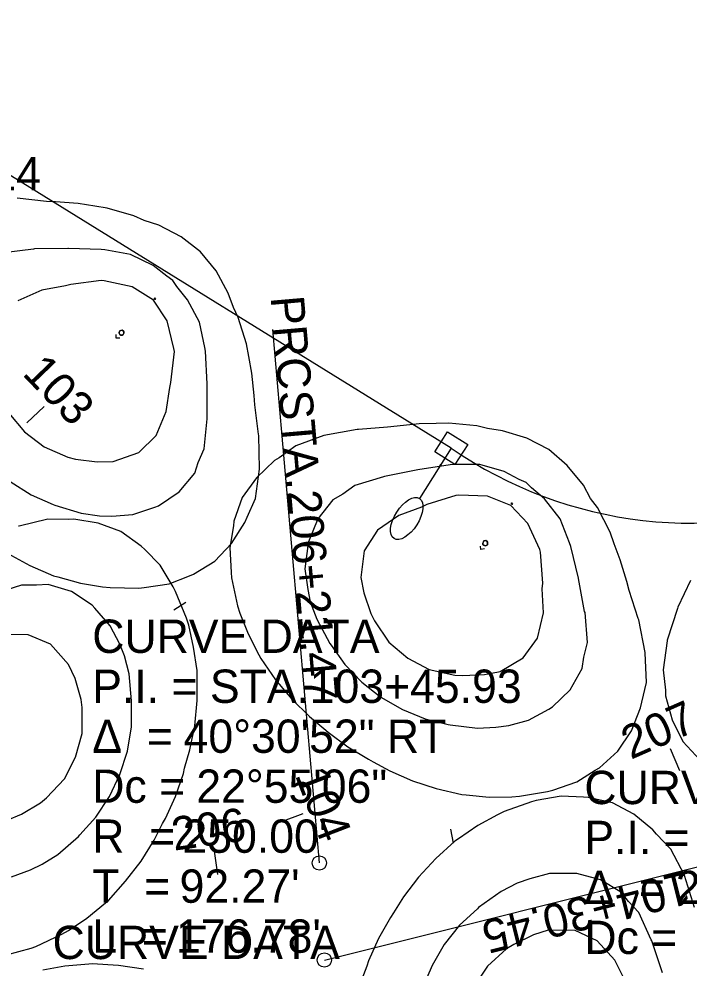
# Model space of a CAD drawing. Extents: x 1598538 to 1602183, y 285823 to 288192.
# Drawn here: x 1600950.3 to 1601091, y 286669.9 to 286869.3 of the extents above; entities that cross this region are included whole.
import ezdxf

# ---------------------------------------------------------------- set-up
doc = ezdxf.new("R2010")
doc.units = 0
for name, color, linetype in [('CM_Corridor_Conceptual', 7, 'Continuous'), ('Default', 7, 'Continuous'), ('MD_P_AGB_B', 7, 'Continuous'), ('PV_P_Curb', 7, 'Continuous'), ('RW_P_Esmt_LA', 7, 'Continuous'), ('RW_P_Esmt_TMP', 7, 'Continuous')]:
    doc.layers.add(name, color=color, linetype=linetype)

msp = doc.modelspace()

# ---------------------------------------------------------------- linework, layer by layer
at = {"layer": 'Default'}
for points in [[(1600947.92, 286756.99), (1600952.55, 286754.46), (1600957.55, 286752.3), (1600958.42, 286752.05), (1600963.17, 286750.74), (1600967.8, 286749.96), (1600969.42, 286749.8), (1600975.42, 286749.68), (1600976.55, 286749.8), (1600981.8, 286750.58), (1600986.05, 286752.27), (1600986.92, 286752.61), (1600991.42, 286755.36), (1600994.92, 286759.08), (1600997.67, 286763.52), (1600998.17, 286764.61), (1600999.92, 286768.55), (1601000.8, 286774.68), (1601000.8, 286774.74), (1601000.67, 286781.77), (1601000.55, 286782.08), (1600999.8, 286788.21), (1600999.67, 286790.18), (1600999.17, 286794.86), (1600998.55, 286798.4), (1600998.05, 286801.02), (1600996.3, 286806.55), (1600995.3, 286808.68), (1600994.17, 286811.71), (1600991.67, 286816.4), (1600988.42, 286820.36), (1600984.3, 286823.52), (1600979.67, 286825.96), (1600976.55, 286826.96), (1600974.42, 286827.93), (1600968.8, 286829.52), (1600966.17, 286829.93), (1600962.67, 286830.49), (1600957.92, 286830.86), (1600956.05, 286830.96), (1600949.92, 286831.65)], [(1600948.42, 286772.11), (1600952.8, 286769.3), (1600957.42, 286767.3), (1600957.8, 286767.11), (1600963.3, 286765.43), (1600967.17, 286764.9), (1600969.8, 286764.83), (1600974.17, 286765.18), (1600978.8, 286766.71), (1600979.55, 286766.99), (1600983.92, 286769.9), (1600987.17, 286773.83), (1600987.92, 286776.11), (1600989.17, 286778.99), (1600989.8, 286785.27), (1600989.8, 286785.49), (1600989.8, 286792.58), (1600989.8, 286792.65), (1600989.42, 286799.46), (1600989.3, 286800.27), (1600988.17, 286805.55), (1600985.67, 286810.3), (1600983.42, 286813.08), (1600982.55, 286814.33), (1600981.3, 286815.27), (1600978.42, 286817.46), (1600973.67, 286819.83), (1600968.3, 286820.77), (1600967.55, 286820.83), (1600960.67, 286821.08), (1600960.55, 286821.08), (1600953.55, 286820.96), (1600953.3, 286820.93), (1600947.05, 286820.15)], [(1600948.17, 286786.49), (1600951.42, 286782.52), (1600955.55, 286779.36), (1600960.55, 286777.24), (1600962.17, 286776.83), (1600966.67, 286776.24), (1600970.05, 286776.33), (1600975.42, 286778.21), (1600979.05, 286781.77), (1600981.17, 286786.8), (1600981.92, 286791.83), (1600982.17, 286792.93), (1600982.92, 286799.43), (1600982.8, 286800.02), (1600981.42, 286805.86), (1600978.55, 286810.21), (1600974.05, 286812.99), (1600968.17, 286814.3), (1600967.55, 286814.33), (1600961.17, 286813.52), (1600960.05, 286813.21), (1600955.05, 286812.33), (1600950.05, 286810.08)], [(1600971.42, 286802.24), (1600970.67, 286802.24), (1600970.67, 286802.99)], [(1601053.8, 286767.24), (1601053.92, 286767.46), (1601053.92, 286767.46), (1601053.8, 286767.24), (1601053.8, 286767.24)], [(1600947.67, 286672.65), (1600952.8, 286674.05), (1600953.8, 286674.4), (1600959.3, 286676.96), (1600960.67, 286677.77), (1600964.55, 286680.36), (1600968.42, 286683.55), (1600969.05, 286684.08), (1600972.67, 286688.11), (1600975.92, 286692.33), (1600978.67, 286696.74), (1600980.42, 286700.27), (1600981.05, 286701.3), (1600983.17, 286705.93), (1600984.8, 286710.77), (1600985.05, 286711.9), (1600986.17, 286715.71), (1600987.17, 286720.8), (1600987.67, 286726.08), (1600987.67, 286731.55), (1600987.67, 286732.36), (1600986.92, 286737.3), (1600985.92, 286741.9), (1600985.42, 286743.4), (1600983.17, 286748.99), (1600982.67, 286749.96), (1600979.92, 286754.49), (1600976.67, 286757.8), (1600975.92, 286758.52), (1600971.67, 286761.61), (1600966.92, 286763.36), (1600961.8, 286764.21), (1600960.67, 286764.15), (1600956.3, 286764.21), (1600950.3, 286762.71), (1600950.17, 286762.71)], [(1601047.8, 286759.43), (1601047.67, 286759.18), (1601047.67, 286759.18), (1601047.8, 286759.43), (1601047.8, 286759.43)], [(1601048.67, 286759.36), (1601048.55, 286759.58), (1601048.55, 286759.58), (1601048.67, 286759.36), (1601048.67, 286759.36)], [(1601048.05, 286757.96), (1601047.3, 286757.83), (1601047.17, 286758.55)], [(1601047.67, 286758.9), (1601047.92, 286758.71), (1601047.92, 286758.71), (1601047.67, 286758.9), (1601047.67, 286758.9)], [(1601048.42, 286758.68), (1601048.67, 286758.83), (1601048.67, 286758.83), (1601048.42, 286758.68), (1601048.42, 286758.68)], [(1601091.3, 286751.3), (1601088.67, 286745.71), (1601088.55, 286745.43), (1601086.42, 286738.74), (1601086.42, 286738.65), (1601085.55, 286732.52), (1601086.05, 286728.24), (1601086.05, 286727.08), (1601087.42, 286722.05), (1601089.67, 286717.46), (1601093.3, 286713.55)], [(1600948.67, 286689.05), (1600952.67, 286690.52), (1600955.17, 286691.68), (1600958.42, 286693.74), (1600962.8, 286697.52), (1600963.05, 286697.86), (1600966.42, 286701.58), (1600969.3, 286705.93), (1600971.42, 286710.55), (1600973.05, 286715.43), (1600973.92, 286720.55), (1600973.92, 286725.55), (1600973.92, 286725.99), (1600973.42, 286731.71), (1600972.42, 286735.46), (1600971.42, 286737.96), (1600969.42, 286741.8), (1600966.17, 286745.49), (1600965.67, 286746.11), (1600961.3, 286748.96), (1600956.42, 286750.46), (1600953.92, 286750.3), (1600950.8, 286750.3), (1600944.8, 286748.46)], [(1600947.8, 286700.93), (1600950.8, 286702.21), (1600954.8, 286704.58), (1600956.05, 286705.61), (1600959.8, 286709.65), (1600962.17, 286714.18), (1600963.55, 286719.15), (1600963.55, 286724.61), (1600963.3, 286726.27), (1600962.05, 286730.68), (1600960.67, 286733.68), (1600956.92, 286737.9), (1600952.17, 286739.9), (1600946.67, 286739.93)], [(1601092.17, 286682.58), (1601090.05, 286689.33), (1601090.05, 286689.4), (1601087.17, 286694.86), (1601084.17, 286698.02), (1601083.42, 286698.93), (1601079.42, 286702.24), (1601074.92, 286704.61), (1601069.8, 286705.74), (1601068.8, 286705.8), (1601064.17, 286705.99), (1601058.92, 286705.05), (1601057.92, 286704.8), (1601052.17, 286702.74), (1601050.8, 286702.05), (1601046.67, 286699.83), (1601042.55, 286697.02), (1601041.8, 286696.55), (1601037.8, 286692.86), (1601034.17, 286688.96), (1601031.05, 286684.83), (1601028.92, 286681.46), (1601028.3, 286680.52), (1601025.8, 286676.08), (1601023.67, 286671.4), (1601023.3, 286670.3), (1601021.92, 286666.61)], [(1601085.42, 286668.86), (1601083.17, 286675.58), (1601083.05, 286675.77), (1601080.42, 286681.52), (1601078.3, 286683.86), (1601076.8, 286685.74), (1601072.42, 286688.4), (1601067.42, 286689.77), (1601066.55, 286689.77), (1601061.67, 286689.74), (1601057.55, 286688.65), (1601054.92, 286687.71), (1601051.55, 286685.96), (1601046.8, 286682.58), (1601046.55, 286682.3), (1601042.8, 286678.9), (1601039.55, 286674.83), (1601037.05, 286670.4), (1601035.05, 286665.71)], [(1601077.67, 286667.05), (1601075.42, 286671.55), (1601071.67, 286675.61), (1601067.05, 286677.77), (1601061.42, 286677.83), (1601058.3, 286676.83), (1601054.17, 286674.8), (1601052.67, 286673.9), (1601048.67, 286670.24), (1601045.8, 286665.96)], [(1600976.42, 286669.65), (1600971.17, 286670.43), (1600965.67, 286670.74), (1600964.92, 286670.68), (1600959.92, 286670.27), (1600955.3, 286669.4)]]:
    msp.add_lwpolyline(points, dxfattribs=at)
for points in [[(1600978.92, 286810.52), (1600978.8, 286810.71), (1600978.67, 286810.52), (1600978.8, 286810.33)], [(1600978.92, 286810.52), (1600978.8, 286810.71), (1600978.67, 286810.52), (1600978.8, 286810.33)], [(1600978.8, 286810.71), (1600978.67, 286810.52), (1600978.67, 286810.52), (1600978.8, 286810.71)], [(1600978.67, 286810.52), (1600978.8, 286810.33), (1600978.8, 286810.33), (1600978.67, 286810.52)], [(1600978.92, 286810.52), (1600978.8, 286810.71), (1600978.8, 286810.71), (1600978.92, 286810.52)], [(1600978.8, 286810.33), (1600978.92, 286810.52), (1600978.92, 286810.52), (1600978.8, 286810.33)], [(1600972.3, 286803.24), (1600972.3, 286803.52), (1600972.17, 286803.74), (1600971.92, 286803.9), (1600971.67, 286803.86), (1600971.42, 286803.74), (1600971.3, 286803.49), (1600971.3, 286803.24), (1600971.42, 286802.99), (1600971.67, 286802.86), (1600971.92, 286802.86), (1600972.17, 286802.99)], [(1600972.3, 286803.24), (1600972.3, 286803.52), (1600972.17, 286803.74), (1600971.92, 286803.9), (1600971.67, 286803.86), (1600971.42, 286803.74), (1600971.3, 286803.49), (1600971.3, 286803.24), (1600971.42, 286802.99), (1600971.67, 286802.86), (1600971.92, 286802.86), (1600972.17, 286802.99)], [(1600971.42, 286803.74), (1600971.3, 286803.49), (1600971.3, 286803.49), (1600971.42, 286803.74)], [(1600971.3, 286803.49), (1600971.3, 286803.24), (1600971.3, 286803.24), (1600971.3, 286803.49)], [(1600971.3, 286803.24), (1600971.42, 286802.99), (1600971.42, 286802.99), (1600971.3, 286803.24)], [(1600971.67, 286803.86), (1600971.42, 286803.74), (1600971.42, 286803.74), (1600971.67, 286803.86)], [(1600971.92, 286803.9), (1600971.67, 286803.86), (1600971.67, 286803.86), (1600971.92, 286803.9)], [(1600972.17, 286803.74), (1600971.92, 286803.9), (1600971.92, 286803.9), (1600972.17, 286803.74)], [(1600972.3, 286803.52), (1600972.17, 286803.74), (1600972.17, 286803.74), (1600972.3, 286803.52)], [(1600972.17, 286802.99), (1600972.3, 286803.24), (1600972.3, 286803.24), (1600972.17, 286802.99)], [(1600972.3, 286803.24), (1600972.3, 286803.52), (1600972.3, 286803.52), (1600972.3, 286803.24)], [(1600971.42, 286802.99), (1600971.67, 286802.86), (1600971.67, 286802.86), (1600971.42, 286802.99)], [(1600971.67, 286802.86), (1600971.92, 286802.86), (1600971.92, 286802.86), (1600971.67, 286802.86)], [(1600971.92, 286802.86), (1600972.17, 286802.99), (1600972.17, 286802.99), (1600971.92, 286802.86)], [(1600995.42, 286763.77), (1600995.3, 286762.8), (1600994.55, 286758.24), (1600994.8, 286752.96), (1600994.92, 286751.83), (1600996.17, 286745.96), (1600996.67, 286744.46), (1600998.42, 286740.08), (1601000.67, 286735.65), (1601001.05, 286734.9), (1601004.17, 286730.43), (1601007.55, 286726.36), (1601011.3, 286722.74), (1601014.3, 286720.21), (1601015.17, 286719.46), (1601019.3, 286716.36), (1601023.67, 286713.74), (1601024.67, 286713.21), (1601028.17, 286711.33), (1601032.92, 286709.24), (1601037.92, 286707.58), (1601043.3, 286706.33), (1601044.17, 286706.24), (1601049.05, 286705.8), (1601053.8, 286705.86), (1601055.42, 286705.99), (1601061.3, 286706.96), (1601062.42, 286707.27), (1601067.42, 286708.99), (1601071.3, 286711.43), (1601072.17, 286711.93), (1601076.05, 286715.43), (1601078.92, 286719.71), (1601080.8, 286724.55), (1601081.05, 286725.71), (1601082.05, 286729.9), (1601081.8, 286736.08), (1601081.8, 286736.15), (1601080.42, 286743.05), (1601080.3, 286743.33), (1601078.42, 286749.21), (1601077.92, 286751.11), (1601076.55, 286755.65), (1601075.3, 286759.02), (1601074.42, 286761.49), (1601071.8, 286766.65), (1601070.3, 286768.55), (1601068.8, 286771.33), (1601065.42, 286775.49), (1601061.55, 286778.83), (1601056.92, 286781.21), (1601051.8, 286782.77), (1601048.67, 286783.21), (1601046.42, 286783.77), (1601040.55, 286784.33), (1601037.92, 286784.3), (1601034.3, 286784.21), (1601029.67, 286783.74), (1601027.67, 286783.49), (1601021.55, 286783.05), (1601021.3, 286783.02), (1601014.3, 286781.8), (1601014.3, 286781.77), (1601008.42, 286779.61), (1601004.92, 286777.11), (1601003.92, 286776.49), (1601000.17, 286772.9), (1600997.17, 286768.74)], [(1601011.05, 286759.43), (1601010.92, 286758.58), (1601010.3, 286753.74), (1601010.92, 286749.43), (1601011.42, 286746.8), (1601012.8, 286743.15), (1601015.55, 286738.08), (1601015.8, 286737.74), (1601018.67, 286733.68), (1601022.3, 286729.93), (1601026.3, 286726.8), (1601030.8, 286724.21), (1601035.55, 286722.24), (1601040.42, 286721.05), (1601040.8, 286720.96), (1601046.55, 286720.3), (1601050.42, 286720.46), (1601053.17, 286720.86), (1601057.3, 286721.96), (1601061.55, 286724.3), (1601062.3, 286724.74), (1601066.05, 286728.36), (1601068.55, 286732.83), (1601068.92, 286735.21), (1601069.67, 286738.27), (1601069.17, 286744.55), (1601069.05, 286744.77), (1601067.8, 286751.71), (1601067.8, 286751.8), (1601066.17, 286758.43), (1601065.92, 286759.21), (1601063.92, 286764.24), (1601060.67, 286768.46), (1601057.92, 286770.77), (1601056.8, 286771.86), (1601055.3, 286772.52), (1601052.17, 286774.18), (1601047.05, 286775.65), (1601041.67, 286775.65), (1601040.8, 286775.58), (1601034.05, 286774.58), (1601034.05, 286774.58), (1601027.05, 286773.18), (1601026.8, 286773.11), (1601020.8, 286771.24), (1601018.3, 286769.46), (1601016.17, 286768.24), (1601013.05, 286764.24)], [(1601022.05, 286751.93), (1601022.67, 286748.68), (1601024.17, 286744.36), (1601024.92, 286742.83), (1601027.92, 286738.33), (1601031.92, 286734.99), (1601036.42, 286732.61), (1601041.8, 286731.43), (1601043.42, 286731.33), (1601048.05, 286731.55), (1601051.3, 286732.21), (1601056.17, 286735.02), (1601059.17, 286739.18), (1601060.42, 286744.52), (1601060.17, 286749.58), (1601060.3, 286750.71), (1601059.8, 286757.24), (1601059.67, 286757.83), (1601057.17, 286763.3), (1601053.55, 286767.05), (1601048.67, 286769.02), (1601042.67, 286769.24), (1601042.05, 286769.18), (1601035.92, 286767.24), (1601034.8, 286766.71), (1601030.05, 286764.99), (1601025.55, 286761.86), (1601022.8, 286757.55)], [(1601053.92, 286767.46), (1601053.8, 286767.61), (1601053.67, 286767.4), (1601053.8, 286767.24)], [(1601053.92, 286767.46), (1601053.8, 286767.61), (1601053.67, 286767.4), (1601053.8, 286767.24)], [(1601053.8, 286767.61), (1601053.67, 286767.4), (1601053.67, 286767.4), (1601053.8, 286767.61)], [(1601053.67, 286767.4), (1601053.8, 286767.24), (1601053.8, 286767.24), (1601053.67, 286767.4)], [(1601053.92, 286767.46), (1601053.8, 286767.61), (1601053.8, 286767.61), (1601053.92, 286767.46)], [(1601048.67, 286759.11), (1601048.67, 286759.36), (1601048.55, 286759.58), (1601048.3, 286759.68), (1601047.92, 286759.61), (1601047.8, 286759.43), (1601047.67, 286759.18), (1601047.67, 286758.9), (1601047.92, 286758.71), (1601048.17, 286758.61), (1601048.42, 286758.68), (1601048.67, 286758.83)], [(1601048.67, 286759.11), (1601048.67, 286759.36), (1601048.55, 286759.58), (1601048.3, 286759.68), (1601047.92, 286759.61), (1601047.8, 286759.43), (1601047.67, 286759.18), (1601047.67, 286758.9), (1601047.92, 286758.71), (1601048.17, 286758.61), (1601048.42, 286758.68), (1601048.67, 286758.83)], [(1601047.92, 286759.61), (1601047.8, 286759.43), (1601047.8, 286759.43), (1601047.92, 286759.61)], [(1601048.3, 286759.68), (1601047.92, 286759.61), (1601047.92, 286759.61), (1601048.3, 286759.68)], [(1601048.55, 286759.58), (1601048.3, 286759.68), (1601048.3, 286759.68), (1601048.55, 286759.58)], [(1601048.67, 286759.11), (1601048.67, 286759.36), (1601048.67, 286759.36), (1601048.67, 286759.11)], [(1601047.67, 286759.18), (1601047.67, 286758.9), (1601047.67, 286758.9), (1601047.67, 286759.18)], [(1601047.92, 286758.71), (1601048.17, 286758.61), (1601048.17, 286758.61), (1601047.92, 286758.71)], [(1601048.17, 286758.61), (1601048.42, 286758.68), (1601048.42, 286758.68), (1601048.17, 286758.61)], [(1601048.67, 286758.83), (1601048.67, 286759.11), (1601048.67, 286759.11), (1601048.67, 286758.83)]]:
    msp.add_lwpolyline(points, close=True, dxfattribs=at)
at = {"layer": 'MD_P_AGB_B'}
for p, q in [((1600951.95, 286784.4), (1600955.55, 286787.87)), ((1600982.8, 286745.17), (1600985.34, 286746.78)), ((1601089.09, 286711.32), (1601087.08, 286715.9)), ((1601005.25, 286700.58), (1601009.92, 286702.37)), ((1601041.56, 286696.1), (1601040.94, 286699.04)), ((1600992.02, 286689.51), (1600991.32, 286694.46))]:
    msp.add_line(p, q, dxfattribs=at)
at = {"layer": 'PV_P_Curb'}
for p, q in [((1601013.35, 286691.95), (1601003.59, 286804.02)), ((1601014.4, 286671.56), (1601123.55, 286698.81))]:
    msp.add_line(p, q, dxfattribs=at)
for centre in [(1601013.35, 286691.95), (1601014.4, 286671.56)]:
    msp.add_circle(centre, 1.5, dxfattribs=at)
at = {"layer": 'RW_P_Esmt_LA'}
msp.add_line((1601041.07, 286779.12), (1601034.38, 286768.56), dxfattribs=at)
msp.add_lwpolyline([(1601044.52, 286779.89), (1601041.84, 286775.67), (1601037.62, 286778.34), (1601040.29, 286782.57)], close=True, dxfattribs=at)
msp.add_ellipse((1601031.71, 286764.33), major_axis=(-2.67, -4.22), ratio=0.5, dxfattribs=at)
at = {"layer": 'RW_P_Esmt_TMP'}
for p, q in [((1601041.07, 286779.12), (1600856.86, 286893.09)), ((1601038.35, 286774.87), (1601038.9, 286775.74))]:
    msp.add_line(p, q, dxfattribs=at)
msp.add_arc((1601091.42, 286851.54), 88.2, 235.1857, 291.6614, dxfattribs=at)

# ---------------------------------------------------------------- texts
at = {"layer": 'CM_Corridor_Conceptual'}
for s, p in [('101+90.14', (1600910.37, 286833.31)), ('CURVE DATA', (1600965.66, 286736.09)), ('P.I. = STA. ', (1600965.66, 286725.59)), ('103+45.93', (1601011.33, 286725.59)), ('Δ  = ', (1600965.66, 286715.09)), ('40°30\'52" RT', (1600984.85, 286715.09)), ('Dc = ', (1600965.66, 286704.59)), ('22°55\'06"', (1600987.51, 286704.59)), ('CURVE DATA', (1601069.01, 286704.32)), ('R  = ', (1600965.66, 286694.09)), ("250.00'", (1600984.61, 286694.09)), ('P.I. = STA. ', (1601069.01, 286693.82)), ('T  = ', (1600965.66, 286683.59)), ("92.27'", (1600984, 286683.59)), ('Δ  = ', (1601069.01, 286683.32)), ('28°25\'54" LT', (1601088.2, 286683.32)), ('L  = ', (1600965.66, 286673.09)), ("176.78'", (1600983.26, 286673.09)), ('Dc = ', (1601069.01, 286672.82)), ('CURVE DATA', (1600957.33, 286671.76))]:
    msp.add_text(s, height=7, dxfattribs=at).set_placement(p)
at = {"layer": 'MD_P_AGB_B'}
for s, rotation, p in [('103', 313.9131, (1600950.78, 286794.63)), ('207', 23.7245, (1601078.76, 286713.61)), ('104', 290.9948, (1601008.16, 286710.46)), ('206', 8.0525, (1600982.83, 286694.52))]:
    msp.add_text(s, height=7, rotation=rotation, dxfattribs=at).set_placement(p)
at = {"layer": 'PV_P_Curb'}
for s, rotation, p in [('PRC', 274.977, (1601003.1, 286810.85)), (' STA. ', 274.977, (1601004.61, 286793.57)), ('206+21.47', 274.977, (1601006.66, 286770.03)), ('104+30.45', 194.0171, (1601090.19, 286690.38))]:
    msp.add_text(s, height=7, rotation=rotation, dxfattribs=at).set_placement(p)

doc.saveas('drawing.dxf')
